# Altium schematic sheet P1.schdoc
size 297 x 209 mm; Symbol: Drawing-Symbol_A4; Company: 嘉立创EDA; Version: V1.0; Page Size: A4; @Project Name: mairui N1; @Update Date: 2026-05-26; @Create Date: 2026-05-26; Device: Drawing-Symbol_A4; @Board Name: Board2; @Page Name: P1; @Create Time: 13:02:53; @Page Count: 1; @Page No: 1; @Schematic Name: Schematic2; @Update Time: 13:02:53; @Assembly Variant: Basic; Border: 1; Title Block Position: 3; Size: A4; Width: 1170; Height: 825; Region Start: 1; X Region Count: 6; Y Region Count: 4; Blade Width: 10
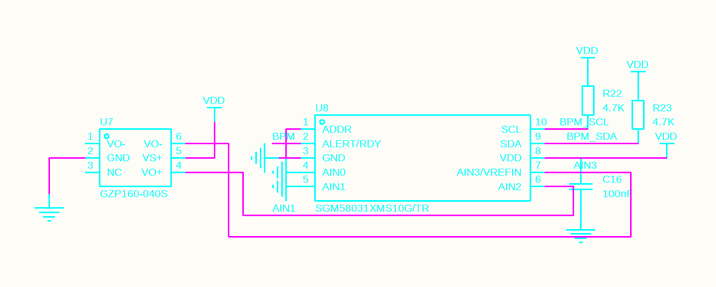
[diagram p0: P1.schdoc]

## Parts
C16  100nF  [C0603]
R22  4.7K  [R0603]
R23  4.7K  [R0603]
U7  GZP160-040S  [SOP-6_L7.0-W7.0-P2.54-LS10.6-BL_GZP160-101S]
U8  SGM58031XMS10G/TR  [MSOP-10_L3.0-W3.0-P0.50-LS4.9-BL]

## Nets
GND: C16.1 U7.2(GND) U8.1(ADDR) U8.3(GND) U8.4(AIN0) U8.5(AIN1)
VDD: C16.2 R22.2 R23.2 U7.5(VS+) U8.8(VDD)
AIN1: U7.4(VO+) U8.6(AIN2)
AIN3: U7.6(VO-) U8.7(AIN3/VREFIN)
BPM: U8.2(ALERT/RDY)
BPM_SCL: R22.1 U8.10(SCL)
BPM_SDA: R23.1 U8.9(SDA)

Not connected (* = marked no-connect by the designer): U7 1(VO-) 3(NC)

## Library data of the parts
C16 = CAP_0603: Symbol: Capacitance; 3D Model: ac125912035d415993ca9572d50418b1; 3D Model Transform: 62.992,31.496,0,0,0,0,0,0,0; ConvertToPcb: yes; ModelName: C0603_L1.6-W0.8-H0.8
R22 R23 = Res_0603: Symbol: 电阻; 3D Model: fc143cca1e79419f9cd78b61e9279f08; 3D Model Transform: 31.8897,63.7794,0,90,0,0,0,0,0; ConvertToPcb: yes
U7 = GZP160-040S_C42402734: 压力范围:0Kpa~40Kpa;接口类型:-;; Manufacturer: Sencoch(芯感智); 3D Model: 8e0cf50f53794993acd16ea34ece44f00819f05c4eef4c71ace90d822a990e87; 3D Model Transform: 275.984,417.322,0,0,0,0,0,0,-15.748; Voltage - Supply: 5V; Module: 否; AddInBom: yes
U8 = SGM58031XMS10G/TR: 分辨率:16位;采样率:-;工作电压:3V~5.5V;接口类型:I2C;; Manufacturer: SGMICRO(圣邦微); 3D Model: 24a4fab644ec4e119b03a4a7433939050819f05c4eef4c71ace90d822a990e87; 3D Model Transform: 118.11,196.85,0,0,0,0,0,0,0; Resolution(Bits): 16位; number of channels: 2；4; Interface: I2C; differential input: 是; Integral non - linearity: 1LSB; Clock/Oscillator: 内置; Clock Frequency: 386kHz~434kHz；410kHz; Programmable Gain: 支持; ADC architecture: Sigma-Delta; Quiescent Current (Iq): 255uA; Full-Scale Range(FSR): 2.048V；512mV；1.024V；4.096V；256mV；6.14V; AddInBom: yes; ModelName: MSOP-10_L3.0-W3.0-H1.1-LS5.0-P0.50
